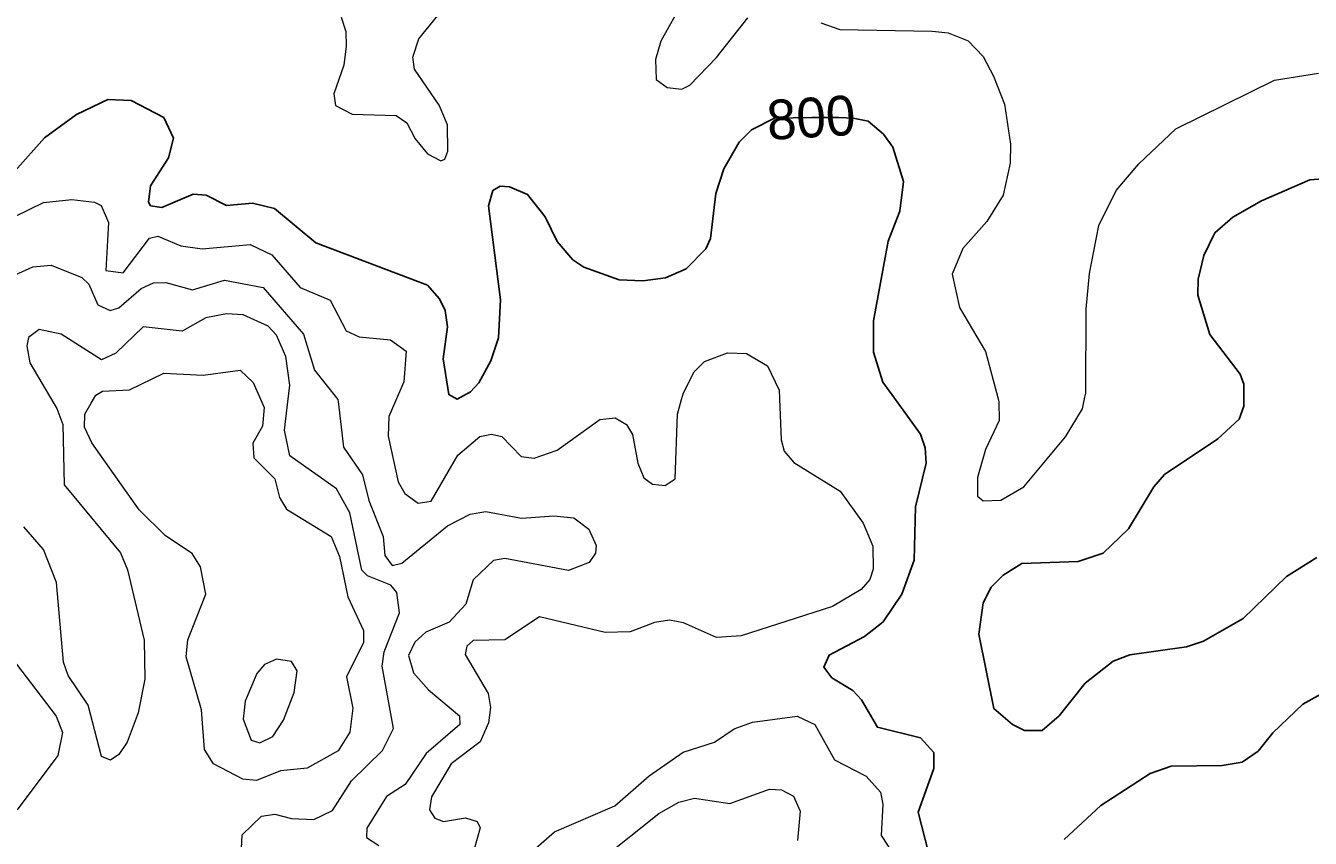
# Model space of a CAD drawing. Extents: x 473.9 to 500, y 7733.1 to 7760.8.
# Drawn here: x 490.243 to 492.833, y 7753.09 to 7754.728 of the extents above; entities that cross this region are included whole.
import ezdxf
from ezdxf.enums import TextEntityAlignment as Align

# ---------------------------------------------------------------- set-up
doc = ezdxf.new("R2010")
doc.units = 0
doc.header["$LTSCALE"] = 0.032
doc.layers.add('1', color=7, linetype='Continuous', lineweight=25)
doc.layers.add('2', color=7, linetype='Continuous', lineweight=13)
doc.layers.add('61', color=7, linetype='Continuous')

msp = doc.modelspace()

# ---------------------------------------------------------------- linework, layer by layer
at = {"layer": '1'}
for points in [[(492.0696, 7753.0351), (492.0423, 7753.1426), (492.0735, 7753.2301), (492.0736, 7753.2629), (492.0468, 7753.2925), (491.9601, 7753.3136), (491.9281, 7753.369), (491.9106, 7753.3875), (491.8684, 7753.4129), (491.852, 7753.435), (491.8629, 7753.4592), (491.9337, 7753.4962), (491.9716, 7753.5261), (492.0091, 7753.5816), (492.0341, 7753.6507), (492.0367, 7753.7581), (492.0582, 7753.8462), (492.0565, 7753.877), (492.0468, 7753.9042), (491.9945, 7753.9769), (491.9711, 7754.0094), (491.9525, 7754.0697), (491.9521, 7754.1332), (491.9816, 7754.2933), (492.0052, 7754.3541), (492.0126, 7754.4141), (491.9913, 7754.4832), (491.9723, 7754.5091), (491.9413, 7754.5351), (491.9111, 7754.5417), (491.8823, 7754.5425), (491.8279, 7754.5425), (491.7526, 7754.5417), (491.7065, 7754.518), (491.6816, 7754.4928), (491.6503, 7754.4396), (491.6344, 7754.3894), (491.6233, 7754.2986), (491.6142, 7754.2778), (491.5749, 7754.2375), (491.5328, 7754.2194), (491.4874, 7754.2133), (491.4397, 7754.2156), (491.3686, 7754.2409), (491.3459, 7754.2561), (491.3148, 7754.293), (491.2905, 7754.3427), (491.2548, 7754.3873), (491.2184, 7754.4032), (491.1997, 7754.4041), (491.1848, 7754.3954), (491.1764, 7754.3647), (491.2004, 7754.1755), (491.1965, 7754.0989), (491.1806, 7754.0521), (491.1566, 7754.0077), (491.1398, 7753.9897), (491.1129, 7753.9752), (491.0959, 7753.9841), (491.0847, 7754.0565), (491.0935, 7754.1208), (491.089, 7754.1537), (491.0773, 7754.1773), (491.0532, 7754.2047), (490.8281, 7754.29), (490.7449, 7754.3596), (490.7004, 7754.37), (490.648, 7754.3653), (490.607, 7754.386), (490.5809, 7754.3884), (490.5175, 7754.3614), (490.4951, 7754.365), (490.4908, 7754.3724), (490.4948, 7754.4052), (490.5315, 7754.4617), (490.5411, 7754.501), (490.5215, 7754.5431), (490.4562, 7754.577), (490.4087, 7754.5789), (490.3456, 7754.5489), (490.2815, 7754.5019), (490.2214, 7754.4346)], [(492.6061, 7754.1845), (492.6067, 7754.2167), (492.6178, 7754.2649), (492.6399, 7754.3104), (492.6765, 7754.3421), (492.7341, 7754.3747), (492.8313, 7754.4172), (492.9011, 7754.4223)], [(492.8455, 7753.6561), (492.7844, 7753.6174), (492.697, 7753.533), (492.6171, 7753.4873), (492.5829, 7753.4757), (492.4687, 7753.4595), (492.4354, 7753.447), (492.379, 7753.4026), (492.3262, 7753.3364), (492.2924, 7753.3071), (492.2567, 7753.3067), (492.232, 7753.3193), (492.1946, 7753.3511), (492.1646, 7753.5014), (492.1734, 7753.5644), (492.1891, 7753.596), (492.2136, 7753.6199), (492.251, 7753.6435), (492.365, 7753.6479), (492.4148, 7753.6642), (492.466, 7753.7133), (492.5175, 7753.798), (492.5389, 7753.8231), (492.646, 7753.8947), (492.6891, 7753.9347), (492.6988, 7753.961), (492.6986, 7753.9812), (492.6983, 7754.005), (492.6909, 7754.0252), (492.6298, 7754.1053), (492.6061, 7754.1845)], [(492.8838, 7753.3972), (492.8178, 7753.3598), (492.757, 7753.3022), (492.7275, 7753.2656), (492.6955, 7753.2432), (492.6547, 7753.2365), (492.5522, 7753.2354)], [(492.5522, 7753.2354), (492.51, 7753.2206), (492.4103, 7753.156), (492.3364, 7753.0874)]]:
    msp.add_lwpolyline(points, dxfattribs=at)
at = {"layer": '2'}
for points in [[(491.5688, 7754.777), (491.5237, 7754.6966), (491.5125, 7754.6596), (491.5141, 7754.6194), (491.5366, 7754.6033), (491.5656, 7754.6001), (491.5817, 7754.6081), (491.6355, 7754.6636), (491.699, 7754.744)], [(490.8789, 7754.7448), (490.8886, 7754.7159), (490.8894, 7754.6869), (490.8846, 7754.6483), (490.8645, 7754.5905), (490.8677, 7754.5671), (490.9014, 7754.5494), (490.9899, 7754.547), (491.0116, 7754.5318), (491.0285, 7754.4996), (491.0534, 7754.4698), (491.0799, 7754.4554), (491.088, 7754.4586), (491.0944, 7754.4747), (491.0936, 7754.5277), (491.0767, 7754.5679), (491.0269, 7754.6403), (491.0237, 7754.6644), (491.0357, 7754.7014), (491.0888, 7754.7665)], [(491.8462, 7754.7336), (491.884, 7754.7199), (492.0705, 7754.7167), (492.1027, 7754.7135), (492.1429, 7754.6974), (492.1734, 7754.666), (492.1943, 7754.6258), (492.216, 7754.5695), (492.2281, 7754.4891), (492.2273, 7754.4506), (492.2136, 7754.3862), (492.1806, 7754.3332), (492.1324, 7754.2785), (492.1107, 7754.227), (492.1252, 7754.1595), (492.1782, 7754.0711), (492.2026, 7753.9781), (492.2048, 7753.9697), (492.2056, 7753.9319), (492.1782, 7753.8733), (492.1621, 7753.817), (492.1621, 7753.7792), (492.1734, 7753.7703), (492.2088, 7753.7711), (492.2554, 7753.7985), (492.339, 7753.899), (492.3736, 7753.9553), (492.3784, 7753.9792), (492.38, 7753.9874), (492.3808, 7754.1563), (492.3873, 7754.2286), (492.4066, 7754.3251), (492.4411, 7754.3959), (492.487, 7754.4497), (492.5617, 7754.5197), (492.7603, 7754.6178), (492.8488, 7754.6323)], [(490.1353, 7754.3016), (490.2795, 7754.3712), (490.3363, 7754.3774), (490.382, 7754.3724), (490.3955, 7754.3654), (490.4101, 7754.3309), (490.4047, 7754.2341), (490.4398, 7754.2295), (490.493, 7754.2998), (490.5097, 7754.3038), (490.5559, 7754.2843), (490.5992, 7754.2779), (490.6956, 7754.2869), (490.7394, 7754.2658), (490.7966, 7754.2), (490.8568, 7754.1747), (490.8891, 7754.1127), (490.9156, 7754.1006), (490.9786, 7754.0949), (491.0102, 7754.0716), (491.0054, 7754.0096), (490.9887, 7753.9707), (490.9756, 7753.9402), (490.9738, 7753.9005), (490.994, 7753.8085), (491.0074, 7753.7851), (491.0346, 7753.7654), (491.0603, 7753.7692), (491.1144, 7753.8624), (491.1587, 7753.8996)], [(490.1724, 7754.2033), (490.2576, 7754.242), (490.2948, 7754.2449), (490.3562, 7754.2202), (490.3709, 7754.2065), (490.389, 7754.165), (490.4137, 7754.154), (490.4314, 7754.1591), (490.4763, 7754.1978), (490.501, 7754.2092), (490.5257, 7754.2099), (490.5797, 7754.1957), (490.6442, 7754.2148), (490.722, 7754.2003), (490.803, 7754.1058), (490.8253, 7754.0334), (490.8726, 7753.9741), (490.8731, 7753.97), (490.8838, 7753.8781), (490.9224, 7753.8224), (490.935, 7753.7709), (490.9641, 7753.6979), (490.9671, 7753.6599), (490.9821, 7753.6397), (491.0012, 7753.6445), (491.0932, 7753.7199), (491.1394, 7753.7429), (491.171, 7753.7484), (491.2428, 7753.735), (491.308, 7753.7398), (491.3479, 7753.7358), (491.3782, 7753.7132), (491.3934, 7753.6797), (491.3917, 7753.6642), (491.3794, 7753.6455), (491.3377, 7753.6297), (491.2091, 7753.6536), (491.1865, 7753.65), (491.145, 7753.6105), (491.1307, 7753.562), (491.0967, 7753.5251), (491.0498, 7753.5051), (491.0277, 7753.4848), (491.0148, 7753.4583), (491.0252, 7753.4234), (491.0554, 7753.3887), (491.1175, 7753.3366), (491.1187, 7753.3194), (491.0505, 7753.2609), (491.008, 7753.1983), (490.9708, 7753.1737), (490.9307, 7753.11), (490.9304, 7753.0915), (490.955, 7753.0749)], [(490.678, 7753.0688), (490.6796, 7753.0969), (490.7186, 7753.1345), (490.7457, 7753.1383), (490.7788, 7753.1293), (490.8244, 7753.1275), (490.8617, 7753.1459), (490.8998, 7753.2052), (490.9624, 7753.2664), (490.985, 7753.3111), (490.9617, 7753.4369), (490.9656, 7753.4658), (490.9965, 7753.5442), (490.9914, 7753.5855), (490.9793, 7753.6003), (490.9321, 7753.619), (490.9209, 7753.6301), (490.8965, 7753.7461), (490.8696, 7753.7939), (490.7755, 7753.8607), (490.7648, 7753.9122), (490.7717, 7753.9694), (490.7758, 7754.0035), (490.768, 7754.0609), (490.7489, 7754.1042), (490.7318, 7754.1223), (490.6817, 7754.1447), (490.6478, 7754.1473), (490.6066, 7754.1391), (490.5585, 7754.112), (490.48, 7754.1208), (490.425, 7754.0677), (490.396, 7754.0543), (490.3149, 7754.1059), (490.2703, 7754.1151)], [(490.2703, 7754.1151), (490.2489, 7754.0995), (490.2457, 7754.0825), (490.2519, 7754.0485), (490.3, 7753.9665), (490.3059, 7753.9563), (490.3181, 7753.9242), (490.3209, 7753.8025), (490.4344, 7753.6652), (490.4486, 7753.6309), (490.4823, 7753.4894), (490.4835, 7753.4103), (490.4702, 7753.3427), (490.4479, 7753.2833), (490.431, 7753.2583), (490.4141, 7753.247), (490.3963, 7753.2548), (490.3694, 7753.3583), (490.329, 7753.4181), (490.3196, 7753.4449), (490.3055, 7753.6052), (490.2793, 7753.6717), (490.2393, 7753.7176)], [(491.1587, 7753.8996), (491.1824, 7753.9046), (491.2028, 7753.8994), (491.2417, 7753.8597), (491.2685, 7753.8557), (491.3144, 7753.872), (491.4007, 7753.934), (491.4315, 7753.9372), (491.4546, 7753.9239), (491.4665, 7753.9037), (491.4771, 7753.8459), (491.4894, 7753.8166), (491.5065, 7753.8037), (491.5325, 7753.8011), (491.5526, 7753.8143), (491.5568, 7753.9445), (491.5652, 7753.9742), (491.569, 7753.9878), (491.591, 7754.0301), (491.6118, 7754.0506), (491.6581, 7754.0683), (491.6959, 7754.0671), (491.7382, 7754.0419), (491.7617, 7753.9932), (491.7624, 7753.9754), (491.7658, 7753.8932), (491.7723, 7753.8701), (491.7918, 7753.8475), (491.885, 7753.7892), (491.9315, 7753.7248), (491.9508, 7753.6789), (491.9514, 7753.6321), (491.9446, 7753.6116), (491.9274, 7753.5913), (491.8694, 7753.5573), (491.6855, 7753.4977), (491.6357, 7753.4948), (491.5693, 7753.5239), (491.541, 7753.5297), (491.5108, 7753.525), (491.462, 7753.5057), (491.4114, 7753.5044), (491.2787, 7753.5364), (491.209, 7753.4901), (491.1456, 7753.4887), (491.1328, 7753.4771), (491.1294, 7753.4603), (491.1752, 7753.3817), (491.1802, 7753.3535), (491.1764, 7753.3223), (491.1591, 7753.2843), (491.1008, 7753.2396), (491.0612, 7753.1731), (491.0572, 7753.1468), (491.0679, 7753.1306), (491.0857, 7753.1233), (491.1298, 7753.1309), (491.1536, 7753.1236), (491.1592, 7753.1109), (491.1472, 7753.0679)], [(490.2245, 7753.4406), (490.3048, 7753.3361), (490.3177, 7753.3033), (490.3078, 7753.2568), (490.2264, 7753.1469)], [(491.2493, 7753.0503), (491.3093, 7753.1025), (491.4307, 7753.1552), (491.4998, 7753.2159), (491.5685, 7753.2631), (491.632, 7753.2834), (491.6714, 7753.3106), (491.7086, 7753.324), (491.7983, 7753.3362), (491.834, 7753.3192), (491.8736, 7753.2478), (491.9374, 7753.2151), (491.9661, 7753.1828), (491.9708, 7753.1587), (491.9676, 7753.0956), (491.9945, 7753.0541)], [(491.4032, 7753.0468), (491.5192, 7753.1396), (491.56, 7753.1627), (491.5912, 7753.1703), (491.6626, 7753.1601), (491.7424, 7753.1889), (491.767, 7753.1871), (491.7906, 7753.1745), (491.8045, 7753.1446), (491.7993, 7753.085)]]:
    msp.add_lwpolyline(points, dxfattribs=at)
for points in [[(490.567, 7753.4552), (490.5701, 7753.4899), (490.6062, 7753.5816), (490.5957, 7753.6369), (490.579, 7753.6637), (490.5253, 7753.6994), (490.4724, 7753.7521), (490.3766, 7753.887), (490.3618, 7753.9188), (490.3627, 7753.9447), (490.3755, 7753.9669), (490.385, 7753.9833), (490.398, 7753.9913), (490.4527, 7753.9939), (490.5219, 7754.0271), (490.6012, 7754.0236), (490.6755, 7754.0334), (490.7019, 7754.0083), (490.7192, 7753.969), (490.7239, 7753.9584), (490.7206, 7753.9203), (490.7009, 7753.8866), (490.7032, 7753.8564), (490.7457, 7753.8145), (490.7552, 7753.7768), (490.7689, 7753.7533), (490.8589, 7753.6978), (490.876, 7753.6577), (490.8924, 7753.5762), (490.9245, 7753.5087), (490.924, 7753.4842), (490.89, 7753.4155), (490.9029, 7753.3522), (490.8964, 7753.3034), (490.8729, 7753.2657), (490.8108, 7753.2311), (490.7567, 7753.2259), (490.7084, 7753.206), (490.6811, 7753.2091), (490.622, 7753.2401), (490.604, 7753.2685), (490.5974, 7753.3489)], [(490.763, 7753.3281), (490.7846, 7753.3838), (490.7904, 7753.4275), (490.7794, 7753.4463), (490.7492, 7753.451), (490.7246, 7753.4398), (490.7095, 7753.4218), (490.6858, 7753.3661), (490.6819, 7753.3297), (490.6978, 7753.2878), (490.7152, 7753.2824), (490.7417, 7753.2947)]]:
    msp.add_lwpolyline(points, close=True, dxfattribs=at)

# ---------------------------------------------------------------- texts
at = {"layer": '61'}
msp.add_text('800', height=0.08, rotation=3.545, dxfattribs=at).set_placement((491.8288, 7754.5028), align=Align.CENTER)

doc.saveas('drawing.dxf')
